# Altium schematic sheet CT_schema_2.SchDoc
size 322 x 229 mm
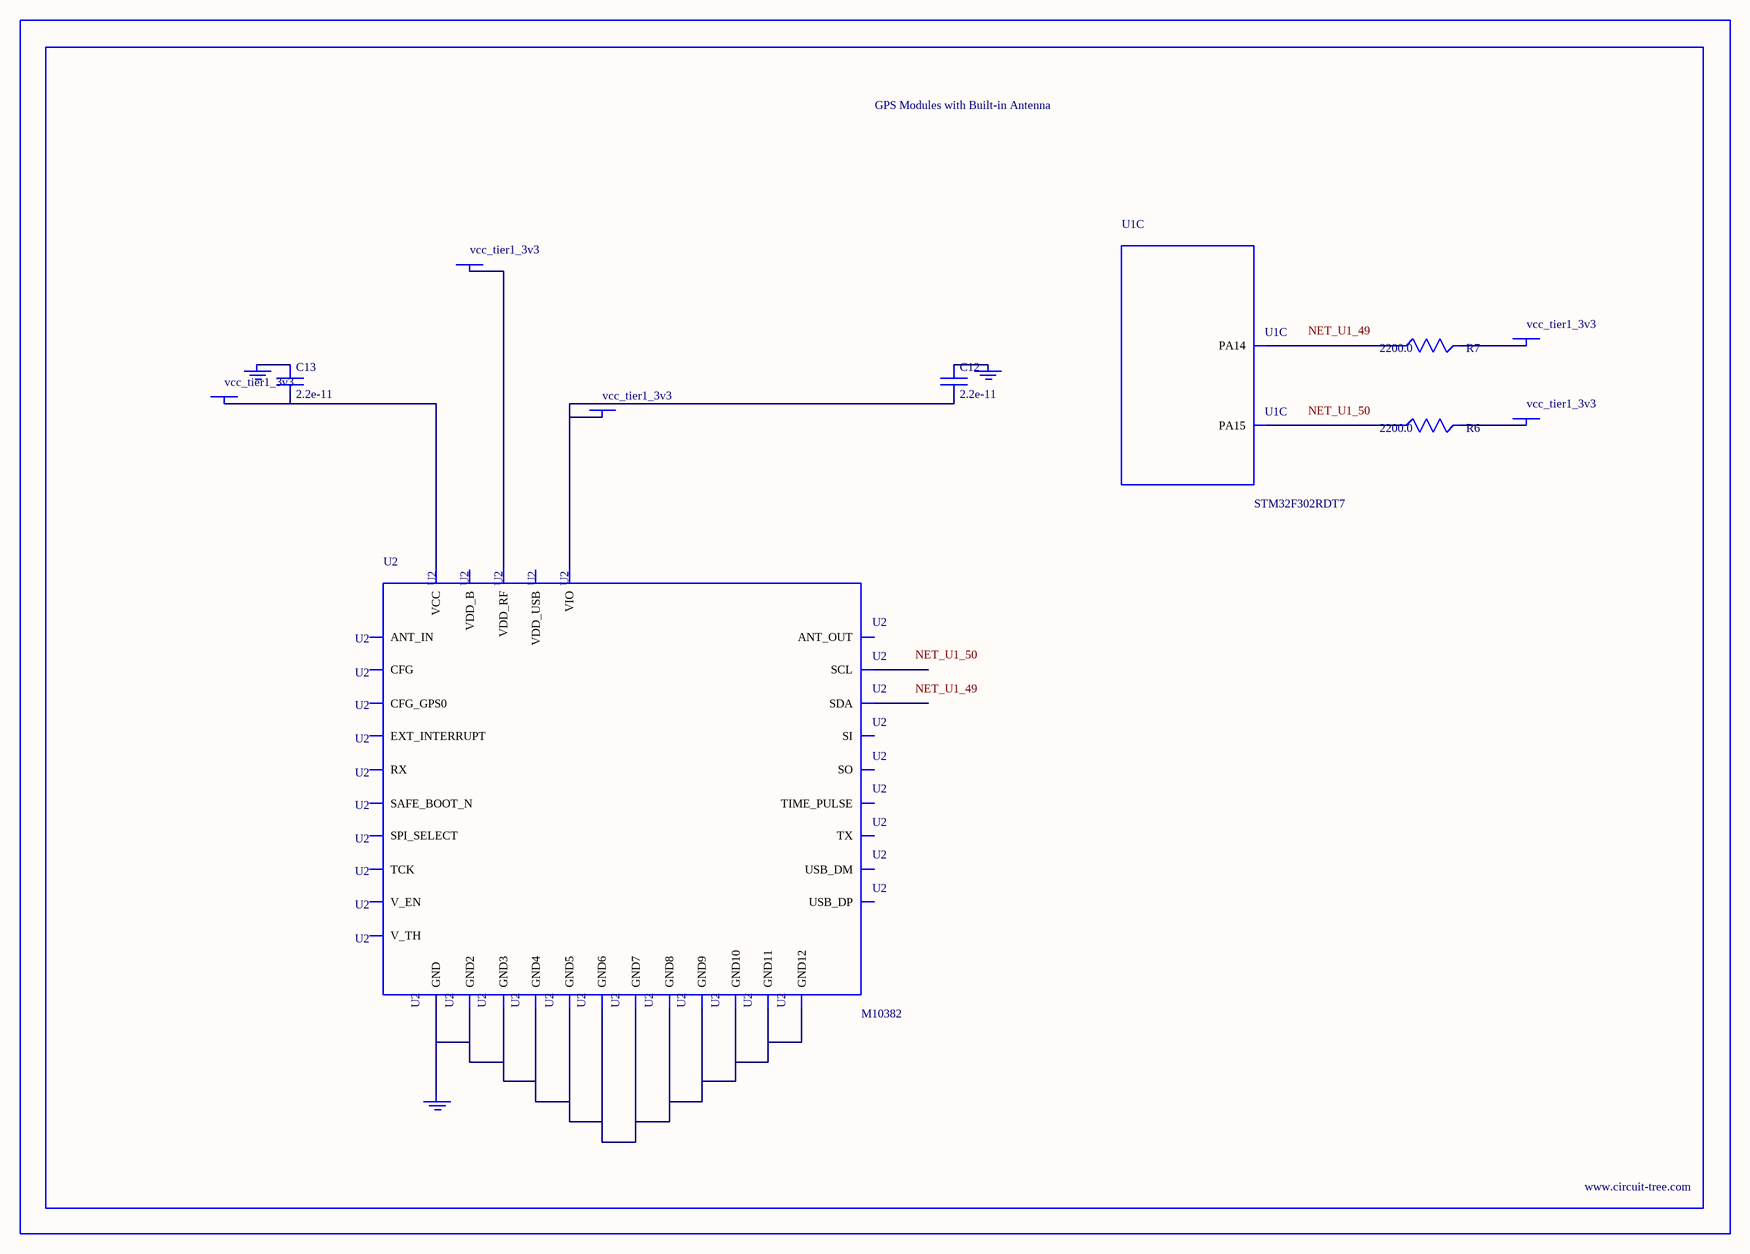
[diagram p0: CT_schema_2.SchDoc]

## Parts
BORDER1  (no value)
C12  2.2e-11  [C0402]
C13  2.2e-11  [C0402]
GND_INSTANCE_1_0  (no value)
GND_INSTANCE_1_1  (no value)
GND_INSTANCE_1_2  (no value)
POWER_INSTANCE_1_0  vcc_tier1_3v3
POWER_INSTANCE_1_1  vcc_tier1_3v3
POWER_INSTANCE_1_2  vcc_tier1_3v3
POWER_INSTANCE_1_3  vcc_tier1_3v3
POWER_INSTANCE_1_4  vcc_tier1_3v3
R6  2200.0  [R0603]
R7  2200.0  [R0603]
U1  STM32F302RDT7  [LQFP64]  (part C of 7)
U2  M10382  [M10382]

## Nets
NetC12_1: C12.1 GND_INSTANCE_1_0.0(GND)
NetC12_2: C12.2 POWER_INSTANCE_1_0.0(PWR) U2.5(VIO)
NetC13_1: C13.1 GND_INSTANCE_1_1.0(GND)
NetC13_2: C13.2 POWER_INSTANCE_1_2.0(PWR) U2.27(VCC)
NetGND_INSTANCE_1_2_0: GND_INSTANCE_1_2.0(GND) U2.2(GND) U2.4(GND2) U2.14(GND3) U2.17(GND4) U2.21(GND5) U2.24(GND6) U2.26(GND7) U2.28(GND8) U2.33(GND9) U2.34(GND10) U2.35(GND11) U2.36(GND12)
NetPOWER_INSTANCE_1_1_0: POWER_INSTANCE_1_1.0(PWR) U2.25(VDD_RF)
NetPOWER_INSTANCE_1_3_0: POWER_INSTANCE_1_3.0(PWR) R7.2
NetPOWER_INSTANCE_1_4_0: POWER_INSTANCE_1_4.0(PWR) R6.2
NetR6_1: R6.1 U1.50(PA15)
NetR7_1: R7.1 U1.49(PA14)

Not connected (* = marked no-connect by the designer): U2 1(ANT_IN) 3(ANT_OUT) 6(USB_DP) 7(USB_DM) 8(SO) 9(CFG_GPS0) 10(SPI_SELECT) 11(TX) 12(V_TH) 13(RX) 15(VDD_B) 16(SI) 18(SDA) 19(SCL) 20(SAFE_BOOT_N) 22(TCK) 23(TIME_PULSE) 29(EXT_INTERRUPT) 30(V_EN) 31(CFG) 32(VDD_USB)

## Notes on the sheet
- Labels drawn without touching a wire or pin: NET_U1_49, NET_U1_50

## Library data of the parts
BORDER1 = BORDER_PAGE1
C12 C13 = C0402C220K3RAC
GND_INSTANCE_1_0-GND_INSTANCE_1_2 = GND
POWER_INSTANCE_1_0-POWER_INSTANCE_1_4 = PWR
R6 R7 = RC0603JR-072K2L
